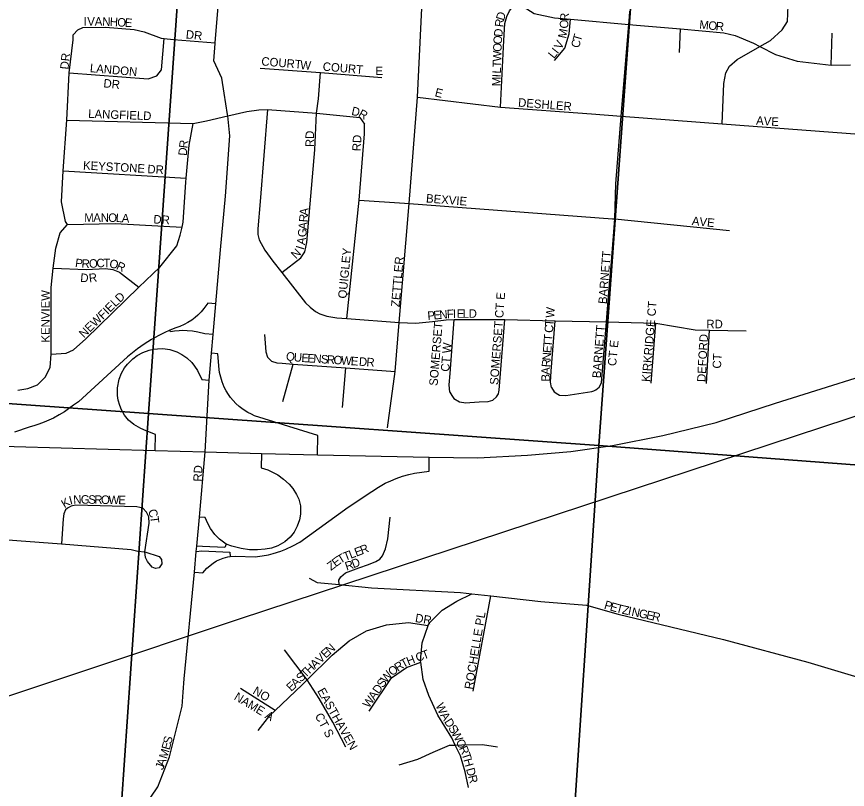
# Model space of a CAD drawing. Extents: x 0 to 34, y 0 to 22.
# Drawn here: x 4.67 to 5.595, y 18.785 to 19.645 of the extents above; entities that cross this region are included whole.
import ezdxf

# ---------------------------------------------------------------- set-up
doc = ezdxf.new("R2010")
doc.units = 0
for name, color, linetype in [('GM_X_City_Street', 7, 'Continuous'), ('GM_X_City_Street_Text', 7, 'Continuous'), ('GM_X_Interchange_Ramps', 7, 'Continuous'), ('GM_X_Interstate_Route', 7, 'Continuous'), ('GM_X_Rail_Line', 7, 'Continuous'), ('GM_X_Section', 7, 'Continuous')]:
    doc.layers.add(name, color=color, linetype=linetype)

msp = doc.modelspace()

# ---------------------------------------------------------------- linework, layer by layer
at = {"layer": 'GM_X_City_Street'}
for points in [[(4.90501, 19.53574), (4.90119, 19.55942), (4.89849, 19.57615), (4.88964, 19.59519), (4.89102, 19.61454), (4.89108, 19.61522), (4.89794, 19.69614), (4.91188, 19.86079), (4.91914, 19.94648), (4.9159, 19.9602), (4.90106, 19.98582), (4.89858, 20.00029), (4.91273, 20.13909), (4.91524, 20.16586), (4.91217, 20.17897), (4.90743, 20.189), (4.90297, 20.19709), (4.89767, 20.20741)], [(5.08284, 19.18724), (5.09167, 19.2496), (5.0961, 19.30438), (5.10696, 19.43668), (5.11652, 19.55494), (5.1227, 19.6848), (5.12738, 19.74282), (5.13414, 19.82636), (5.13615, 19.85044), (5.13655, 19.85519), (5.13715, 19.86239)], [(5.2038, 19.73632), (5.20214, 19.71529), (5.20386, 19.69969), (5.2105, 19.68251), (5.21948, 19.67063), (5.22773, 19.66217), (5.23412, 19.65564), (5.24618, 19.64791), (5.2689, 19.6431), (5.28671, 19.64155), (5.35154, 19.63593), (5.36447, 19.63481), (5.40928, 19.63083), (5.45739, 19.62655), (5.46988, 19.62338), (5.49029, 19.61517), (5.49765, 19.61131), (5.51482, 19.60235), (5.53903, 19.59486), (5.57683, 19.59065), (5.59859, 19.59077)], [(5.20889, 19.54386), (5.21242, 19.61788), (5.21378, 19.63687), (5.21577, 19.64483), (5.21887, 19.65088), (5.22773, 19.66217)], [(5.45539, 19.52512), (5.45751, 19.5703), (5.45954, 19.58206), (5.4638, 19.58962), (5.47224, 19.59674), (5.49765, 19.61131), (5.5093, 19.61799), (5.52234, 19.63001), (5.52814, 19.63907), (5.5291, 19.65692)], [(5.32914, 19.33351), (5.3322, 19.37159), (5.33611, 19.41956), (5.33703, 19.45838), (5.34318, 19.5337), (5.35154, 19.63593), (5.35226, 19.64486), (5.35273, 19.65062)], [(4.73832, 19.62976), (4.74402, 19.6324), (4.76906, 19.63271), (4.80092, 19.63033), (4.81229, 19.62764), (4.83125, 19.62075), (4.83441, 19.62038), (4.8449, 19.61918), (4.89108, 19.61522)], [(5.26874, 19.59559), (5.28028, 19.60953), (5.2854, 19.62543), (5.28671, 19.64155)], [(4.67163, 19.22887), (4.68264, 19.23073), (4.69328, 19.23488), (4.70202, 19.24359), (4.70736, 19.25421), (4.7085, 19.26892), (4.7086, 19.29143), (4.70868, 19.32219), (4.70873, 19.34308), (4.71103, 19.36469), (4.71378, 19.38712), (4.71876, 19.40383), (4.72675, 19.4133), (4.72448, 19.41672), (4.71999, 19.43839), (4.72206, 19.47294), (4.72605, 19.52923), (4.72871, 19.58194), (4.73298, 19.61876), (4.733, 19.62446), (4.73832, 19.62976)], [(5.40817, 19.60468), (5.40928, 19.63083)], [(5.57683, 19.59065), (5.57811, 19.62597)], [(4.72871, 19.58194), (4.81671, 19.57521), (4.8262, 19.5786), (4.83154, 19.58542), (4.83441, 19.62038)], [(4.94118, 19.58736), (5.00832, 19.58222)], [(5.00616, 19.55293), (5.00617, 19.55296), (5.00832, 19.58222)], [(5.00832, 19.58222), (5.07659, 19.57669)], [(4.96542, 19.35998), (4.98652, 19.37603), (4.9911, 19.38286), (4.9934, 19.39311), (5.00202, 19.4964), (5.00413, 19.5371), (5.00616, 19.55293)], [(5.11652, 19.55494), (5.20889, 19.54386), (5.3102, 19.53622), (5.34318, 19.5337), (5.45539, 19.52512), (5.70203, 19.50676), (5.8447, 19.49493)], [(4.72605, 19.52923), (4.8666, 19.52566), (4.88156, 19.52853), (4.90524, 19.53433), (4.92636, 19.53886), (4.93972, 19.54093), (4.94932, 19.54112), (5.00413, 19.5371), (5.05217, 19.53216), (5.05755, 19.525)], [(4.94932, 19.54112), (4.94118, 19.43892), (4.93876, 19.40854), (4.93878, 19.40225), (4.94012, 19.39619), (4.94639, 19.38477), (4.95554, 19.37248), (4.96542, 19.35998), (4.99181, 19.32619), (4.99703, 19.32119), (5.0029, 19.31655), (5.00771, 19.31401), (5.01548, 19.31119), (5.02645, 19.30953), (5.03792, 19.30877), (5.0961, 19.30438), (5.11446, 19.30339), (5.13293, 19.30536), (5.14825, 19.30717), (5.15736, 19.30767), (5.21375, 19.30748), (5.26963, 19.30619), (5.32682, 19.30483), (5.38186, 19.30369), (5.42564, 19.29606), (5.44157, 19.2958), (5.48217, 19.29513)], [(4.89725, 19.38524), (4.90252, 19.44464), (4.90737, 19.51187), (4.90524, 19.53433), (4.90501, 19.53574)], [(4.7085, 19.26892), (4.72523, 19.2701), (4.73359, 19.27387), (4.74728, 19.28599), (4.80636, 19.34344), (4.82944, 19.36588), (4.84847, 19.38937), (4.85229, 19.40152), (4.85444, 19.41048), (4.85574, 19.41594), (4.85852, 19.46037), (4.85896, 19.46496), (4.86242, 19.50138), (4.8666, 19.52566)], [(5.03792, 19.30877), (5.05152, 19.44047), (5.05734, 19.51428), (5.05755, 19.525)], [(4.72206, 19.47294), (4.85896, 19.46496)], [(5.05152, 19.44047), (5.10186, 19.43703)], [(5.10186, 19.43703), (5.10696, 19.43668), (5.33334, 19.41977)], [(4.72675, 19.4133), (4.77986, 19.41427), (4.85444, 19.41048)], [(5.33334, 19.41977), (5.33611, 19.41956), (5.46387, 19.40648)], [(4.85572, 18.89285), (4.85683, 18.90768), (4.86826, 19.02649), (4.87022, 19.04966), (4.87066, 19.05559), (4.87373, 19.08778), (4.88009, 19.16043), (4.88438, 19.23991), (4.88705, 19.27011), (4.88889, 19.29086), (4.89192, 19.32507), (4.89725, 19.38524)], [(4.71103, 19.36469), (4.74748, 19.3631), (4.76911, 19.36416), (4.77746, 19.36338), (4.78465, 19.36032), (4.80636, 19.34344)], [(5.32682, 19.30483), (5.32914, 19.33351)], [(5.15254, 19.22667), (5.15152, 19.23475), (5.1526, 19.24748), (5.15736, 19.30767)], [(5.20025, 19.21801), (5.20436, 19.22149), (5.20643, 19.22502), (5.20689, 19.227), (5.20735, 19.22899), (5.21375, 19.30748)], [(5.2654, 19.23208), (5.26436, 19.23801), (5.26528, 19.24993), (5.26963, 19.30619)], [(5.31872, 19.23248), (5.32116, 19.23713), (5.32682, 19.30483)], [(5.3766, 19.2368), (5.38186, 19.30369)], [(4.94628, 19.29104), (4.94755, 19.27169), (4.94952, 19.26576), (4.95393, 19.26134), (4.95986, 19.25941), (4.96561, 19.259), (4.97817, 19.25808), (5.03671, 19.25388), (5.09167, 19.2496)], [(5.438, 19.23639), (5.44157, 19.2958)], [(4.96638, 19.21619), (4.97817, 19.25808)], [(5.03275, 19.20952), (5.03671, 19.25388)], [(5.15254, 19.22667), (5.15472, 19.22293), (5.15679, 19.21971), (5.16302, 19.21606), (5.17016, 19.21494), (5.17467, 19.21524), (5.18516, 19.21592), (5.19508, 19.21646), (5.20025, 19.21801)], [(5.2654, 19.23208), (5.26856, 19.22695), (5.27247, 19.2247), (5.27463, 19.22346), (5.28164, 19.22313), (5.3105, 19.22736), (5.31276, 19.2283), (5.31502, 19.22924), (5.31872, 19.23248)], [(4.81354, 19.04286), (4.81285, 19.04902), (4.81787, 19.08093), (4.81741, 19.08822), (4.8149, 19.09324), (4.81057, 19.09757), (4.80396, 19.09916), (4.7358, 19.10099), (4.73079, 19.10008), (4.72691, 19.0978), (4.72463, 19.09575), (4.72258, 19.09141), (4.72213, 19.08595), (4.72007, 19.05813)], [(5.02916, 19.01274), (5.02881, 19.01768), (5.0311, 19.02147), (5.03643, 19.02562), (5.05125, 19.03127), (5.06188, 19.03503), (5.06986, 19.03841), (5.07443, 19.04105), (5.07748, 19.04484), (5.08093, 19.05242), (5.08325, 19.06341), (5.08602, 19.08769)], [(4.36138, 19.07294), (4.36253, 19.0743), (4.36842, 19.07854), (4.37417, 19.08128), (4.38005, 19.08224), (4.46113, 19.07717), (4.72007, 19.05813), (4.7978, 19.05152), (4.8051, 19.0497), (4.81285, 19.04902), (4.82881, 19.044), (4.83154, 19.04058), (4.83177, 19.03557), (4.82881, 19.03146), (4.8247, 19.03055), (4.8211, 19.03204), (4.81604, 19.0383), (4.81354, 19.04286)], [(4.99582, 19.0197), (5.0049, 19.01511), (5.02916, 19.01274), (5.06518, 19.00921), (5.16414, 19.00393), (5.17673, 19.0025), (5.19816, 19.00006), (5.2536, 18.99375), (5.3044, 18.98978), (5.33962, 18.97979), (5.45706, 18.95168), (5.551, 18.92631), (5.63621, 18.90059), (5.79566, 18.84687)], [(5.17325, 18.78685), (5.16952, 18.80432), (5.16427, 18.82218), (5.15846, 18.83414), (5.15449, 18.84233), (5.13903, 18.86744), (5.12887, 18.8891), (5.12287, 18.90697), (5.12009, 18.92647), (5.1199, 18.92785), (5.12148, 18.94796), (5.12834, 18.96702), (5.12912, 18.9692), (5.14395, 18.98433), (5.16028, 18.99415), (5.17673, 19.0025)], [(5.17852, 18.89425), (5.19816, 19.00006)], [(4.9389, 18.85026), (4.95221, 18.86691), (4.95805, 18.87247), (4.98794, 18.90096), (4.99365, 18.90664), (5.0214, 18.93425), (5.04039, 18.95013), (5.05975, 18.96108), (5.08176, 18.96784), (5.10639, 18.97042), (5.12834, 18.96702)], [(4.99365, 18.90664), (4.96836, 18.94012)], [(5.0625, 18.87187), (5.08763, 18.90898), (5.10434, 18.92031), (5.12009, 18.92647)], [(5.03661, 18.83171), (5.0223, 18.85947), (5.00684, 18.8861), (4.99365, 18.90664)], [(4.7239, 18.6283), (4.72484, 18.62983), (4.77251, 18.70418), (4.81173, 18.76462), (4.82742, 18.78771), (4.84024, 18.82091), (4.85457, 18.8775), (4.85572, 18.89285)], [(4.95805, 18.87247), (4.91934, 18.89701)], [(5.09603, 18.81216), (5.11689, 18.81855), (5.13397, 18.82608), (5.15218, 18.83399), (5.15846, 18.83414), (5.16583, 18.83432), (5.18894, 18.83463), (5.20561, 18.83229)]]:
    msp.add_lwpolyline(points, dxfattribs=at)
at = {"layer": 'GM_X_Interchange_Ramps'}
for points in [[(4.89192, 19.32507), (4.88318, 19.32593), (4.87876, 19.31974), (4.87558, 19.31596), (4.87202, 19.31235), (4.86909, 19.30979), (4.86534, 19.30694), (4.86095, 19.3041), (4.8568, 19.30187), (4.85185, 19.29972), (4.84759, 19.29824), (4.84062, 19.29569), (4.83453, 19.29294), (4.82835, 19.28986), (4.82036, 19.2854), (4.81226, 19.2803), (4.80463, 19.27493), (4.79721, 19.26909), (4.79344, 19.26587), (4.73921, 19.21598), (4.73342, 19.21212), (4.72808, 19.20815), (4.7233, 19.20493), (4.71771, 19.20153), (4.71113, 19.19799), (4.70606, 19.19557), (4.70102, 19.19342), (4.69474, 19.19107), (4.69031, 19.18963), (4.68415, 19.1879), (4.66776, 19.18226)], [(4.88889, 19.29086), (4.87956, 19.29177), (4.87203, 19.29363), (4.86582, 19.29463), (4.86019, 19.29511), (4.8553, 19.29522), (4.85094, 19.29508), (4.84578, 19.29461), (4.8414, 19.29395), (4.84062, 19.29569)], [(4.82438, 19.16196), (4.82482, 19.17972), (4.81449, 19.18354), (4.80845, 19.18635), (4.80077, 19.19081), (4.79476, 19.19559), (4.79033, 19.20116), (4.78694, 19.20703), (4.7849, 19.21192), (4.78327, 19.21774), (4.78245, 19.22313), (4.78244, 19.23155), (4.78431, 19.2411), (4.7869, 19.24773), (4.79041, 19.25381), (4.79364, 19.25799), (4.79945, 19.26384), (4.80454, 19.26765), (4.81068, 19.27101), (4.81757, 19.27352), (4.82251, 19.27461), (4.82704, 19.27513), (4.83288, 19.27517), (4.84076, 19.27404), (4.84847, 19.27156), (4.85421, 19.26867), (4.85955, 19.26498), (4.86508, 19.25981), (4.86834, 19.2558), (4.87155, 19.25072), (4.87631, 19.2407), (4.88438, 19.23991)], [(5.00511, 19.15692), (5.00561, 19.17847), (4.93505, 19.20035), (4.93173, 19.20229), (4.92744, 19.20408), (4.92219, 19.20746), (4.91773, 19.21095), (4.91423, 19.21417), (4.9111, 19.2175), (4.90833, 19.2209), (4.90597, 19.22419), (4.90347, 19.22828), (4.90137, 19.23231), (4.89894, 19.23817), (4.89732, 19.24335), (4.89616, 19.24851), (4.89562, 19.25214), (4.89411, 19.26942), (4.88705, 19.27011)], [(4.86826, 19.02649), (4.87754, 19.02559), (4.8819, 19.03076), (4.88885, 19.03663), (4.89261, 19.03893), (4.90006, 19.04213), (4.90526, 19.04348), (4.90798, 19.04374), (4.91372, 19.04428), (4.93565, 19.04355), (4.94354, 19.04451), (4.95073, 19.04589), (4.95593, 19.04719), (4.96425, 19.04982), (4.96998, 19.05206), (4.97768, 19.05566), (4.98537, 19.06), (5.03911, 19.09877), (5.06543, 19.11633), (5.07291, 19.12118), (5.08048, 19.12536), (5.08665, 19.12827), (5.0927, 19.13075), (5.09976, 19.13317), (5.10679, 19.13512), (5.11309, 19.13648), (5.12935, 19.13901), (5.1294, 19.15428)], [(4.94287, 19.15867), (4.94252, 19.1424), (4.94971, 19.14018), (4.95518, 19.13783), (4.96091, 19.13465), (4.96736, 19.13001), (4.97352, 19.12422), (4.97751, 19.11948), (4.98186, 19.11291), (4.98449, 19.10761), (4.98603, 19.10032), (4.98616, 19.091), (4.98512, 19.08483), (4.98265, 19.07759), (4.97905, 19.07105), (4.97471, 19.0656), (4.96883, 19.06036), (4.96112, 19.05583), (4.95377, 19.05336), (4.94676, 19.05203), (4.93818, 19.05126), (4.92951, 19.05142), (4.92013, 19.05264), (4.90973, 19.05536), (4.90355, 19.05775), (4.89602, 19.06313), (4.89098, 19.06836), (4.88601, 19.07505), (4.88287, 19.0806), (4.88, 19.08716), (4.87373, 19.08778)], [(4.87022, 19.04966), (4.87643, 19.05013), (4.90751, 19.04876), (4.90798, 19.04374)], [(4.90355, 19.05775), (4.90202, 19.05379), (4.87716, 19.05489), (4.87066, 19.05559)]]:
    msp.add_lwpolyline(points, dxfattribs=at)
at = {"layer": 'GM_X_Interstate_Route'}
msp.add_lwpolyline([(4.25462, 19.17728), (4.30598, 19.17356), (4.48331, 19.16879), (4.66732, 19.16631), (4.82438, 19.16196), (4.88009, 19.16043), (4.94287, 19.15867), (5.00511, 19.15692), (5.1294, 19.15428), (5.18364, 19.15385), (5.23891, 19.1567), (5.28726, 19.1607), (5.33366, 19.16744), (5.38937, 19.17841), (5.44903, 19.19311), (5.51501, 19.21445), (5.66134, 19.26044)], dxfattribs=at)
at = {"layer": 'GM_X_Rail_Line'}
msp.add_lwpolyline([(3.24228, 18.42761), (4.04049, 18.68141), (4.91721, 18.97414), (5.62605, 19.20739), (5.83323, 19.2746), (5.99342, 19.32068), (6.0587, 19.33616), (6.12886, 19.34558), (6.1917, 19.34977), (6.29642, 19.34768), (6.6636, 19.31587)], dxfattribs=at)
at = {"layer": 'GM_X_Section'}
for points in [[(4.3834, 20.24774), (4.88792, 20.20946), (4.8168, 19.2029), (4.31376, 19.23853)], [(4.88792, 20.20946), (5.39107, 20.17129), (5.31842, 19.16738), (4.8168, 19.2029)], [(5.39107, 20.17129), (5.8928, 20.13549), (5.81902, 19.1295), (5.31842, 19.16738)], [(4.8168, 19.2029), (4.74693, 18.19068), (4.24183, 18.22667), (4.31376, 19.23853)], [(5.31842, 19.16738), (5.25066, 18.15589), (5.18855, 18.15922), (4.74693, 18.19068), (4.8168, 19.2029)], [(5.81902, 19.1295), (5.74839, 18.11688), (5.25066, 18.15589), (5.31842, 19.16738)]]:
    msp.add_lwpolyline(points, close=True, dxfattribs=at)

# ---------------------------------------------------------------- texts
at = {"layer": 'GM_X_City_Street_Text'}
for s, height, rotation, p in [('I', 0.00947, 359.9563, (4.74465, 19.63451)), ('V', 0.00947, 359.97035, (4.74882, 19.63451)), ('A', 0.00947, 359.95628, (4.75715, 19.63451)), ('N', 0.00947, 358.11997, (4.7654, 19.6345)), ('H', 0.00947, 356.78501, (4.77367, 19.63423)), ('O', 0.00947, 356.71954, (4.78199, 19.63376)), ('E', 0.00947, 356.72246, (4.79031, 19.63329)), ('D', 0.00947, 73.74241, (5.21258, 19.63953)), ('R', 0.00947, 86.84171, (5.28449, 19.63943)), ('R', 0.00947, 82.64606, (5.2117, 19.63247)), ('O', 0.00947, 87.1106, (5.28407, 19.63112)), ('M', 0.00947, 354.72806, (5.42981, 19.63117)), ('O', 0.00947, 354.75553, (5.43977, 19.63025)), ('R', 0.00947, 354.30874, (5.44805, 19.62949)), ('DR', 0.00947, 353.99459, (4.85817, 19.62033)), ('D', 0.00947, 84.87878, (5.21073, 19.62178)), ('M', 0.00947, 78.08778, (5.2818, 19.61972)), ('T', 0.00947, 74.08837, (5.29809, 19.6162)), ('O', 0.00947, 88.09812, (5.20997, 19.60527)), ('O', 0.00947, 86.65407, (5.21024, 19.61354)), ('V', 0.00947, 62.32199, (5.27616, 19.60732)), ('C', 0.00947, 75.03885, (5.29617, 19.60899)), ('W', 0.00947, 88.1217, (5.20961, 19.59445)), ('I', 0.00947, 51.25595, (5.27245, 19.6024)), ('DR', 0.00947, 83.99458, (4.72788, 19.58542)), ('COURT', 0.00947, 355.13323, (4.9423, 19.59034)), ('L', 0.00947, 51.23351, (5.26828, 19.5972)), ('LANDON', 0.00947, 355.15482, (4.75147, 19.58284)), ('W', 0.00947, 355.60387, (4.98562, 19.58617)), ('COURT', 0.00947, 355.13362, (5.01063, 19.58451)), ('E', 0.00947, 0.00001, (5.06965, 19.57951)), ('L', 0.00947, 88.1145, (5.20917, 19.58112)), ('T', 0.00947, 88.0872, (5.20939, 19.58778)), ('I', 0.00947, 88.14043, (5.20904, 19.57696)), ('DR', 0.00947, 353.98321, (4.76648, 19.56598)), ('M', 0.00947, 88.1054, (5.20871, 19.56695)), ('E', 0.00947, 345.97019, (5.13509, 19.55612)), ('DESHLER', 0.00947, 355.46124, (5.22813, 19.54451)), ('LANGFIELD', 0.00947, 357.79859, (4.74972, 19.53201)), ('D', 0.00947, 347.44275, (5.04231, 19.53535)), ('R', 0.00947, 330.93596, (5.04978, 19.53379)), ('AVE', 0.00947, 356.04938, (5.49311, 19.52451)), ('RD', 0.00947, 90, (5.00121, 19.4994)), ('RD', 0.00947, 86.98901, (5.05316, 19.49457)), ('R', 0.00947, 82.52251, (4.86019, 19.49768)), ('D', 0.00947, 85.44873, (4.85954, 19.4895)), ('KEYSTONE', 0.00947, 356.86246, (4.74392, 19.47451)), ('DR', 0.00947, 356.98842, (4.81558, 19.47034)), ('BEXVIE', 0.00947, 355.51381, (5.12562, 19.43784)), ('A', 0.00947, 85.3398, (4.9945, 19.423)), ('M', 0.00947, 359.98179, (4.74549, 19.41618)), ('A', 0.00947, 359.97814, (4.75549, 19.41618)), ('N', 0.00947, 359.97814, (4.76382, 19.41617)), ('O', 0.00947, 359.38794, (4.77213, 19.41617)), ('L', 0.00947, 357.62202, (4.78038, 19.41608)), ('A', 0.00947, 357.17908, (4.78702, 19.41581)), ('DR', 0.00947, 356.98902, (4.82225, 19.41451)), ('R', 0.00947, 85.33061, (4.99389, 19.41552)), ('AVE', 0.00947, 354.09695, (5.4215, 19.41284)), ('A', 0.00947, 85.30817, (4.99321, 19.40721)), ('G', 0.00947, 85.09399, (4.99249, 19.39887)), ('A', 0.00947, 81.87508, (4.99125, 19.39004)), ('N', 0.00947, 45.12361, (4.98125, 19.37431)), ('I', 0.00947, 73.11538, (4.9897, 19.38451)), ('QUIGLEY', 0.00947, 84.472, (5.0373, 19.33054)), ('BARNETT', 0.00947, 85.53209, (5.32708, 19.32453)), ('P', 0.00947, 352.73941, (4.7349, 19.36616)), ('R', 0.00947, 356.89124, (4.74226, 19.36525)), ('O', 0.00947, 3.89658, (4.75102, 19.36485)), ('C', 0.00947, 3.74299, (4.75932, 19.36542)), ('T', 0.00947, 358.57951, (4.76658, 19.3659)), ('O', 0.00947, 346.49917, (4.77272, 19.36581)), ('ZETTLER', 0.00947, 85.23515, (5.09633, 19.3212)), ('R', 0.00947, 334.32571, (4.78033, 19.36404)), ('D', 0.00947, 354.87879, (4.74073, 19.34959)), ('R', 0.00947, 7.02113, (4.75118, 19.34888)), ('KENVIEW', 0.00947, 90, (4.70704, 19.2819)), ('NEWFIELD', 0.00947, 44.4423, (4.74504, 19.28647)), ('SOMERSET CT E', 0.0094697, 85.68218, (5.20621, 19.23453)), ('KIRKRIDGE CT', 0.0094697, 85.33363, (5.37538, 19.23788)), ('F', 0.00947, 4.29392, (5.14942, 19.30881)), ('I', 0.00947, 2.14213, (5.15597, 19.3093)), ('E', 0.00947, 0.21858, (5.16005, 19.30945)), ('L', 0.00947, 0.00001, (5.16671, 19.30948)), ('D', 0.00947, 0.00001, (5.17337, 19.30948)), ('W', 0.00947, 85.45804, (5.26837, 19.30904)), ('P', 0.00947, 4.86799, (5.12785, 19.30697)), ('E', 0.00947, 4.84077, (5.13449, 19.30754)), ('N', 0.00947, 4.87916, (5.14114, 19.3081)), ('SOMERSET', 0.00947, 85.36334, (5.1387, 19.23354)), ('C', 0.00947, 85.44871, (5.26705, 19.29241)), ('T', 0.00947, 85.455, (5.26765, 19.29989)), ('BARNETT', 0.00947, 85.53182, (5.32037, 19.24204)), ('RD', 0.00947, 0.00001, (5.43798, 19.29781)), ('T', 0.00947, 85.455, (5.26632, 19.28327)), ('DEFORD', 0.00947, 86.93149, (5.43704, 19.23782)), ('CT W', 0.00947, 84.96036, (5.15162, 19.24918)), ('T', 0.00947, 85.455, (5.2658, 19.27663)), ('CT E', 0.00947, 84.28507, (5.33742, 19.25545)), ('E', 0.00947, 85.455, (5.26527, 19.26998)), ('Q', 0.00947, 350.86828, (4.96944, 19.26254)), ('U', 0.00947, 354.92477, (4.97839, 19.26113)), ('E', 0.00947, 356.24105, (4.98693, 19.26037)), ('E', 0.00947, 356.34373, (4.9936, 19.25993)), ('N', 0.00947, 356.3255, (5.00026, 19.2595)), ('S', 0.00947, 356.32955, (5.00857, 19.25897)), ('R', 0.00947, 356.32973, (5.01523, 19.25854)), ('O', 0.00947, 356.3255, (5.02271, 19.25806)), ('W', 0.00947, 356.3283, (5.03103, 19.25753)), ('E', 0.00947, 356.30949, (5.04184, 19.25684)), ('D', 0.00947, 356.3255, (5.05099, 19.25625)), ('R', 0.00947, 356.31939, (5.0593, 19.25571)), ('R', 0.00947, 85.5752, (5.26403, 19.2542)), ('N', 0.00947, 85.44873, (5.26461, 19.26167)), ('CT', 0.00947, 86.81007, (5.45414, 19.25276)), ('A', 0.00947, 87.81419, (5.26372, 19.24597)), ('B', 0.00947, 89.87855, (5.2637, 19.23856)), ('RD', 0.00947, 86.97755, (4.87621, 19.12699)), ('K', 0.00947, 31.68338, (4.72348, 19.09742)), ('I', 0.00947, 14.3119, (4.72987, 19.1015)), ('N', 0.00947, 1.90187, (4.73337, 19.10246)), ('G', 0.00947, 359.36608, (4.74159, 19.10273)), ('S', 0.00947, 359.15306, (4.74991, 19.10264)), ('R', 0.00947, 359.16269, (4.75658, 19.10254)), ('O', 0.00947, 359.15948, (4.76408, 19.10243)), ('W', 0.00947, 359.16247, (4.77241, 19.10231)), ('E', 0.00947, 359.15306, (4.78324, 19.10216)), ('C', 0.00947, 291.4542, (4.81615, 19.09457)), ('T', 0.00947, 277.3419, (4.81875, 19.08818)), ('T', 0.00947, 21.01005, (5.03589, 19.03889)), ('L', 0.00947, 21.01005, (5.04212, 19.04128)), ('E', 0.00947, 21.01005, (5.04834, 19.04367)), ('R', 0.00947, 21.58234, (5.05466, 19.04609)), ('E', 0.00947, 36.58577, (5.02542, 19.0318)), ('T', 0.00947, 31.05276, (5.03057, 19.03564)), ('D', 0.00947, 21.29627, (5.04513, 19.03073)), ('Z', 0.00947, 36.58577, (5.02007, 19.02783)), ('R', 0.00947, 18.58855, (5.03757, 19.02817)), ('P', 0.00947, 343.37925, (5.3235, 18.9861)), ('E', 0.00947, 343.37298, (5.32988, 18.9842)), ('T', 0.00947, 345.43994, (5.33663, 18.98219)), ('Z', 0.00947, 347.72788, (5.34349, 18.98042)), ('I', 0.00947, 347.92951, (5.35004, 18.979)), ('N', 0.00947, 347.88845, (5.35411, 18.97812)), ('DR', 0.00947, 350.54359, (5.11328, 18.97115)), ('ROCHELLE PL', 0.0094697, 80.53806, (5.17789, 18.89553)), ('G', 0.00947, 347.91355, (5.36226, 18.97638)), ('E', 0.00947, 347.88616, (5.37041, 18.97463)), ('R', 0.00947, 347.90496, (5.37693, 18.97323)), ('E', 0.00947, 43.62825, (5.01435, 18.93015)), ('N', 0.00947, 41.9076, (5.01912, 18.9347)), ('T', 0.00947, 20.37058, (5.12331, 18.92906)), ('V', 0.00947, 43.90028, (5.00836, 18.92438)), ('T', 0.00947, 28.50798, (5.10063, 18.91954)), ('H', 0.00947, 21.13167, (5.1062, 18.92259)), ('C', 0.00947, 20.36277, (5.11628, 18.92645)), ('H', 0.00947, 43.87185, (4.99634, 18.91283)), ('A', 0.00947, 43.88437, (5.00235, 18.91861)), ('O', 0.00947, 36.76498, (5.08809, 18.91049)), ('R', 0.00947, 34.63985, (5.09469, 18.91542)), ('S', 0.00947, 43.8925, (4.98673, 18.90358)), ('T', 0.00947, 43.89866, (4.99154, 18.90821)), ('W', 0.00947, 50.95425, (5.08171, 18.9025)), ('E', 0.00947, 43.89866, (4.97592, 18.89318)), ('A', 0.00947, 43.87185, (4.98072, 18.8978)), ('S', 0.00947, 55.25645, (5.07802, 18.89717)), ('NAME A', 0.00947, 329.21644, (4.91139, 18.88527)), ('NO', 0.00947, 329.53614, (4.93222, 18.89177)), ('EASTHAVEN', 0.00947, 299.32092, (5.00455, 18.89442)), ('A', 0.00947, 55.26006, (5.06853, 18.88348)), ('D', 0.00947, 55.27564, (5.07328, 18.89032)), ('W', 0.00947, 55.25592, (5.06235, 18.87458)), ('W', 0.00947, 294.12809, (5.13632, 18.87835)), ('CT S', 0.00947, 298.29976, (5.00188, 18.86669)), ('A', 0.00947, 301.38191, (5.14136, 18.86731)), ('D', 0.00947, 302.25926, (5.14578, 18.86006)), ('S', 0.00947, 302.24283, (5.15023, 18.85301)), ('W', 0.00947, 298.5729, (5.15371, 18.84751)), ('E', 0.00947, 75.55866, (4.84046, 18.82815)), ('S', 0.00947, 75.57457, (4.84213, 18.83461)), ('O', 0.00947, 295.55826, (5.15883, 18.83812)), ('M', 0.00947, 73.30409, (4.83748, 18.81818)), ('R', 0.00947, 294.65301, (5.16241, 18.83063)), ('T', 0.00947, 288.72009, (5.16544, 18.82406)), ('H', 0.00947, 285.23979, (5.16753, 18.81789)), ('J', 0.00947, 69.87873, (4.83298, 18.80585)), ('A', 0.00947, 69.89095, (4.83442, 18.80977)), ('D', 0.00947, 285.04496, (5.17037, 18.80745)), ('R', 0.00947, 285.04736, (5.17253, 18.7994))]:
    msp.add_text(s, height=height, rotation=rotation, dxfattribs=at).set_placement(p)

doc.saveas('drawing.dxf')
